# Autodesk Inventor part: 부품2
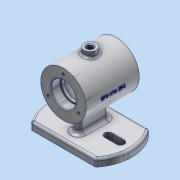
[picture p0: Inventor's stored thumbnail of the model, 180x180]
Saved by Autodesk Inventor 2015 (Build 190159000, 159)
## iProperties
Created: 2017-12
Part Number: 부품2
Material: 알루미늄 6061
Document SubType Name: Modeling
Designer: SCD-A03
Density: 2.7 g/cm^3
Appearance: 알루미늄 - 평지
Author: SCD-A03
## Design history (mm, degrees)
node "스케치1"
sketch "스케치2"
  geometry: L1 (-42.426, 35)-(42.426, 35); L2 (42.426, -35)-(-42.426, -35); A1 r 55 centre (0, 0) between (-42.426, 35) and (-42.426, -35); A2 r 55 centre (0, 0) between (42.426, -35) and (42.426, 35); 2 further points
  constraints: 4 end point, 4 point on circle, 2 centre point, 1 coincident, 1 horizontal, 1 midpoint, 1 parallel, 1 vertical alignment
  dimensions: "d2" = 84.85281 distance of L2.start L2.end; "d3" = 55 radius of A1; "d4" = 70 distance between parallel lines of L2 L1; "d5" = 55 radius of A2
extrude "돌출1" new body sketch "스케치2" distance "d6" = 10; taper "d7" = 0 deg
sketch "스케치3"
  geometry: L1 (-40, 0)-(-24, 0); L2 (-40, -5)-(-24, -5); L3 (-24, 5)-(-40, 5); A1 r 55 centre (0, 0) between (-42.426, 35) and (-42.426, -35) reference; A2 r 5 centre (-40, 0) between (-40, 5) and (-40, -5); A3 r 5 centre (-24, 0) between (-24, -5) and (-24, 5); 1 further point
  constraints: 8 end point, 4 point on circle, 4 tangent, 2 centre point, 1 horizontal, 1 horizontal alignment, 1 midpoint, 1 parallel
  dimensions: "d8" = 16 distance of L3.start L3.end; "d9" = 24 horizontal distance of A1.centre L3.start; "d11" = 5 radius of A2
extrude "돌출2" cut sketch "스케치3" distance "d12" = 10; taper "d13" = 0 deg
sketch "스케치8"
  geometry: L1 (0, -15)-(0, 15); L2 (-5, -15)-(-5, 15); L3 (5, 15)-(5, -15); A1 r 55 centre (0, 0) between (-42.426, 35) and (-42.426, -35) reference; A2 r 5 centre (0, -15) between (-5, -15) and (5, -15); A3 r 5 centre (0, 15) between (5, 15) and (-5, 15); 1 further point
  constraints: 8 end point, 4 point on circle, 4 tangent, 2 centre point, 1 coincident, 1 midpoint, 1 parallel, 1 vertical
  dimensions: "d18" = 5 radius of A2; "d19" = 30 distance of L3.start L3.end
extrude "돌출4" join sketch "스케치8" distance "d20" = 52; taper "d21" = 0 deg
sketch "스케치9"
  geometry: L1 (-42.426, 0)-(42.426, 0) reference; C1 r 30 at (0, 62); 1 further point
  constraints: 1 centre point
  dimensions: "d22" = 60 diameter of C1; "d23" = 62 distance from line of L1 C1.centre
extrude "돌출5" join sketch "스케치9" stored distance "d24" = 70; taper "d25" = 0 deg
hole "구멍1" diameter "d28" = 32; stored, may be unused: countersink angle "d32" = 90 deg, drill point angle "d34" = 0 deg; dims "d29" = 6, "d30" = 4, "d31" = 2, "d33" = 12, "d44" = 10, "d45" = 10
hole "구멍2" diameter "d37" = 28; stored, may be unused: countersink angle "d41" = 90 deg, drill point angle "d43" = 0 deg; dims "d35" = 10, "d36" = 10, "d38" = 6, "d39" = 4, "d40" = 2, "d42" = 3
hole "구멍3" diameter "d48" = 50; stored, may be unused: countersink angle "d52" = 90 deg, drill point angle "d54" = 0 deg; dims "d46" = 10, "d47" = 10, "d49" = 6, "d50" = 4, "d51" = 2, "d53" = 20
fillet "모깎기1" dims "d55" = 3
chamfer "모따기1" distance "d56" = 1; stored, may be unused: second distance "d57" = 2, angle "d58" = 45 deg
chamfer "모따기2" distance "d59" = 1; stored, may be unused: second distance "d60" = 2, angle "d61" = 45 deg
node "작업 평면1"
sketch "스케치11"
  geometry: C1 r 8 at (0, 0); 1 further point
  constraints: 1 centre point, 1 coincident
  dimensions: "d63" = 16 diameter of C1
extrude "돌출6" join sketch "스케치11" stored distance "d64" = 70; taper "d65" = 0 deg
hole "구멍4" diameter "d68" = 8; stored, may be unused: countersink angle "d72" = 90 deg, drill point angle "d74" = 0 deg; dims "d66" = 10, "d67" = 10, "d69" = 6, "d70" = 4, "d71" = 2, "d73" = 20
sketch "스케치12"
  geometry: C1 r 30 at (0, 0) reference; 2 further points
  constraints: 1 vertical alignment
  dimensions: "d75" = 23 distance of C1.centre point (0, 23)
hole "구멍5" sketch "스케치12" at (0, 23) diameter "d76" = 3.242; stored, may be unused: countersink angle "d80" = 90 deg, drill point angle "d82" = 118 deg; dims "d77" = 8, "d78" = 4, "d79" = 2, "d81" = 10
fillet "모깎기2" dims "d86" = 0.3
chamfer "모따기3" distance "d88" = 1; stored, may be unused: second distance "d89" = 2, angle "d90" = 45 deg
fillet "모깎기4" dims "d91" = 3
fillet "모깎기5" dims "d92" = 5
fillet "모깎기6" dims "d93" = 3
fillet "모깎기7" dims "d94" = 3
node "작업 평면2"
sketch "스케치13"
  geometry: L1 (35, 7)-(35, 0) reference; L2 (35, 0)-(5, 0) reference; L3 (5, 0)-(5, 10) reference; L4 (5, 10)-(32, 10) reference; L5 (-32, 10)-(-5, 10) reference; L6 (-5, 10)-(-5, 0) reference; L7 (-5, 0)-(-35, 0) reference; L8 (-35, 0)-(-35, 7) reference; L9 (-35, 62)-(35, 62) reference; L10 (35, 7)-(35, 0) reference; L11 (35, 0)-(5, 0) reference; L12 (5, 0)-(5, 10) reference; L13 (5, 10)-(32, 10) reference; L14 (-32, 10)-(-5, 10) reference; L15 (-5, 10)-(-5, 0) reference; L16 (-5, 0)-(-35, 0) reference; L17 (-35, 0)-(-35, 7) reference; L18 (-35, 62)-(35, 62) reference; L19 (-35, 92)-(-35, 32) reference; L20 (-35, 92)-(35, 92) reference; A1 r 3 centre (32, 7) between (35, 7) and (32, 10) reference; A2 r 3 centre (-32, 7) between (-32, 10) and (-35, 7) reference; A3 r 3 centre (32, 7) between (35, 7) and (32, 10) reference; A4 r 3 centre (-32, 7) between (-32, 10) and (-35, 7) reference; 2 further points
  constraints: 1 other
  dimensions: "d97" = 35 distance from line of L19 point (0, 62); "d98" = 30 distance from line of point (0, 62) L20
feature "엠보싱1" sketch "스케치13" dims "d99" = 1, "d100" = 0
node "솔리드1"
mirror "대칭1"
mirror "대칭3"
pattern_circular "원형 패턴1" dims angle "d84" = 360 deg
mirror "대칭4"
node "절단 모서리 투영1"
node "절단 모서리 투영2"
other parameters: "d62" = 99
